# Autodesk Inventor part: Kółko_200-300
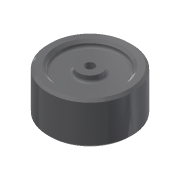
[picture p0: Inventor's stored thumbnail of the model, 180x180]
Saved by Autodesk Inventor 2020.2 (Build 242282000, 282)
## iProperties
Created: 2010-12
Part Number: Kółko_200-300
Document SubType Name: Modeling
Designer: F.Stasiak
Density: 1 g/cm^3
Material: Ogólny
Appearance: Gładki - średnioszary
Manager: www.cadconsulting.pl
Company: Fabian Stasiak CAD Consulting
Author: F.Stasiak
Subject: Zbiór ćwiczeń. Autodesk Inventor 2020. Kurs podstawowy
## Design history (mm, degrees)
sketch "Szkic1"
  geometry: C1 r 35 at (0, 0); C2 r 3.75 at (0, 0); 1 further point
  constraints: 2 centre point, 2 coincident
  dimensions: "d0" = 70 diameter of C1; "d1" = 7.5 diameter of C2
extrude "Wyciągnięcie proste1" new body sketch "Szkic1" distance "d2" = 20; taper "d3" = 0 deg
sketch "Szkic2"
  geometry: L1 (-35, 20)-(35, 20) reference; L2 (-35, 0)-(35, 0) reference; L3 (-26, 20)-(-10, 20); L4 (-10, 20)-(-10, 15); L5 (-10, 15)-(-26, 15); L6 (-26, 15)-(-26, 20); L7 (-26, 5)-(-10, 5); L8 (-10, 5)-(-10, 0); L9 (-10, 0)-(-26, 0); L10 (-26, 0)-(-26, 5); L11 (0, -4)-(0, 24) reference; 1 further point
  constraints: 16 end point, 5 collinear, 4 parallel, 2 horizontal, 2 perpendicular
  dimensions: "d4" = 16 distance of L4.end L5.end; "d5" = 5 distance of L3.end L4.end; "d6" = 20 diameter of L4 L11
revolve "Obrót1" sketch "Szkic2" stored, may be unused: angle "d7" = 90 deg
fillet "Zaokrąglenie1" dims "d8" = 2
feature "Przesunięcie powierzchni2"
chamfer "Faza3" distance "d16" = 2; stored, may be unused: second distance "d17" = 2, angle "d18" = 45 deg
node "Bryła1"
other parameters: "d12" = 0
